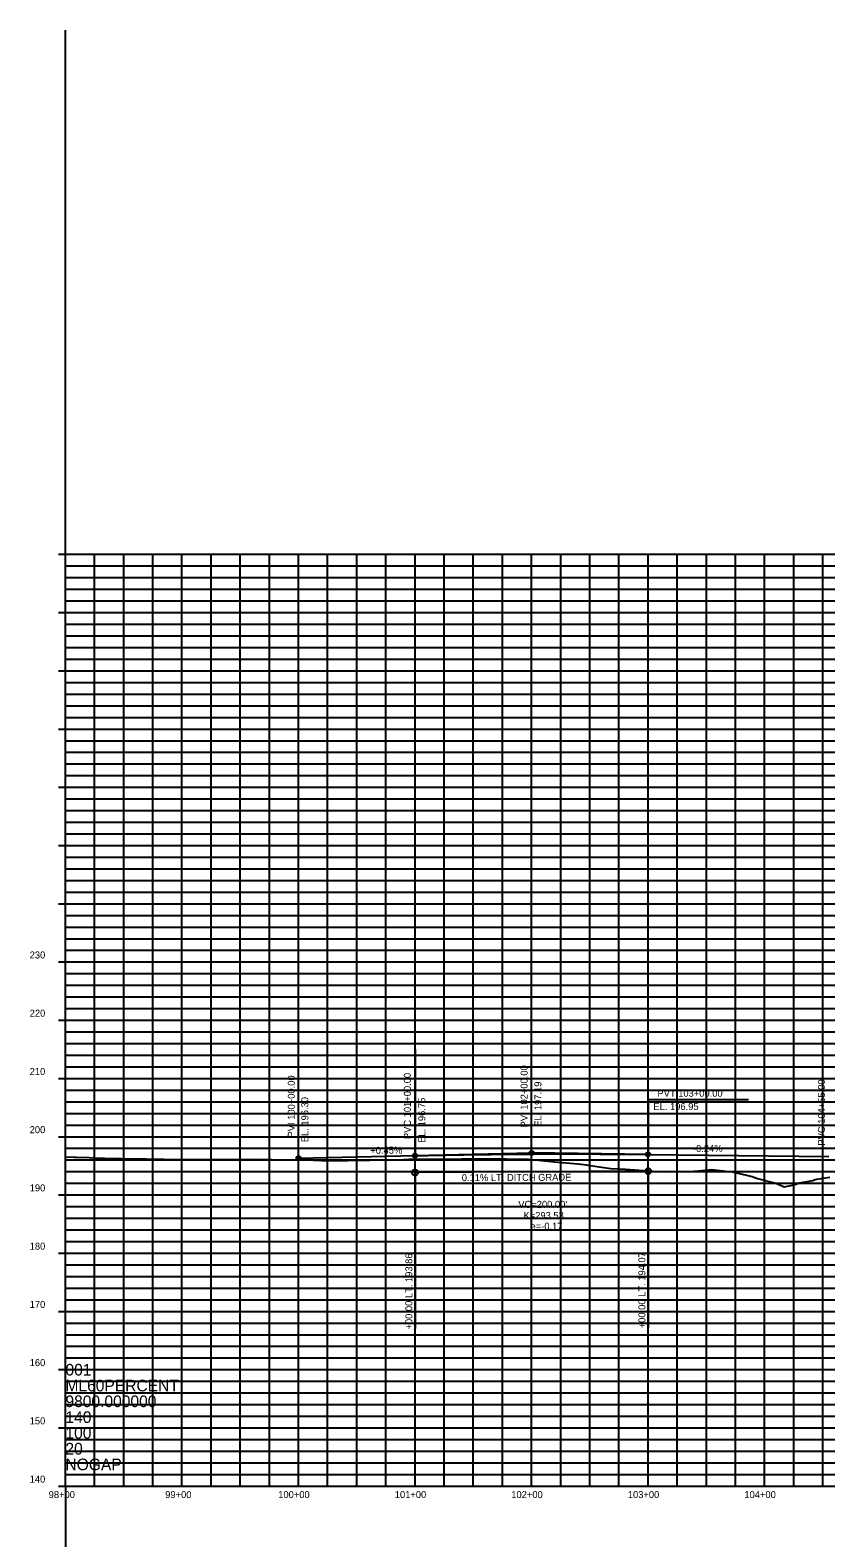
# Model space of a CAD drawing. Extents: x 1384498 to 1391279, y 1965973 to 1976560.
# Drawn here: x 1388219 to 1388901, y 1975265 to 1976560 of the extents above; entities that cross this region are included whole.
import ezdxf

# ---------------------------------------------------------------- set-up
doc = ezdxf.new("R2010")
doc.units = 0
for name, color, linetype in [('Default', 7, 'Continuous'), ('R_Axis_Annotation', 7, 'Continuous'), ('R_Exist Surface', 7, 'Continuous'), ('R_Grid', 7, 'Continuous'), ('R_Grid Annot', 7, 'Continuous'), ('R_Grid_Minor', 7, 'Continuous'), ('R_Vert Alg', 7, 'Continuous'), ('R_Vert Alg Annot', 7, 'Continuous')]:
    doc.layers.add(name, color=color, linetype=linetype)

msp = doc.modelspace()

# ---------------------------------------------------------------- linework, layer by layer
at = {"layer": 'Default'}
for q in [(1388248.8, 1976559.8), (1390648.8, 1975309.8), (1388248.8, 1974059.8)]:
    msp.add_line((1388248.8, 1975309.8), q, dxfattribs=at)
at = {"layer": 'R_Exist Surface'}
msp.add_lwpolyline([(1388248.8, 1975592.4), (1388256.2, 1975592.1), (1388258.4, 1975592.1), (1388269.2, 1975591.8), (1388273.4, 1975591.6), (1388282.2, 1975591.4), (1388288.4, 1975591.2), (1388296.8, 1975591), (1388303.4, 1975590.8), (1388313.1, 1975590.8), (1388318.4, 1975590.7), (1388328.7, 1975590.5), (1388333.4, 1975590.4), (1388337.8, 1975590.3), (1388348.4, 1975590.2), (1388352.2, 1975590.2), (1388363.4, 1975590.2), (1388366.2, 1975590.2), (1388378.4, 1975590.2), (1388384.7, 1975590.3), (1388393.4, 1975590.3), (1388406.3, 1975590.3), (1388408.4, 1975590.4), (1388410.8, 1975590.3), (1388423.4, 1975590.3), (1388426, 1975590.3), (1388438.4, 1975590), (1388439.1, 1975590), (1388442.9, 1975590), (1388451.8, 1975589.9), (1388453.4, 1975589.9), (1388461.8, 1975589.6), (1388468.4, 1975589.4), (1388476.7, 1975589.4), (1388483.4, 1975589.4), (1388490.7, 1975589.4), (1388498.4, 1975589.5), (1388500.4, 1975589.6), (1388503.8, 1975589.6), (1388509.9, 1975589.7), (1388513.5, 1975589.8), (1388518.3, 1975589.9), (1388523.5, 1975589.9), (1388526.1, 1975589.9), (1388528.5, 1975589.9), (1388533.7, 1975590), (1388539.1, 1975590.2), (1388541.4, 1975590.3), (1388543.6, 1975590.4), (1388548.3, 1975590.4), (1388552, 1975590.4), (1388558.7, 1975590.4), (1388561.5, 1975590.4), (1388563.6, 1975590.4), (1388573.8, 1975590.5), (1388574.1, 1975590.5), (1388588.8, 1975590.8), (1388596.3, 1975590.9), (1388598, 1975590.8), (1388604.1, 1975590.9), (1388613.2, 1975590.9), (1388618.8, 1975590.9), (1388627, 1975590.9), (1388640.4, 1975590.5), (1388641.3, 1975590.5), (1388643.2, 1975590.4), (1388646.3, 1975590.4), (1388666, 1975588.4), (1388668.6, 1975588.1), (1388688.6, 1975586.4), (1388693.6, 1975585.8), (1388708.7, 1975583.6), (1388716.7, 1975582.6), (1388729.5, 1975581.8), (1388740.8, 1975581.1), (1388757.5, 1975580), (1388764.5, 1975579.6), (1388775.8, 1975580.1), (1388780, 1975579.7), (1388791.8, 1975580.6), (1388803.6, 1975581.6), (1388805.6, 1975581.4), (1388805.8, 1975581.3), (1388818, 1975580), (1388819.9, 1975579.8), (1388838.2, 1975575.5), (1388842.7, 1975573.8), (1388858.4, 1975570), (1388865.5, 1975566.6), (1388874.1, 1975568.4), (1388878.7, 1975570.2), (1388890.2, 1975572.3), (1388892.3, 1975572.9), (1388893.7, 1975573.4), (1388904.8, 1975574.9)], dxfattribs=at)
at = {"layer": 'R_Grid'}
for p, q in [((1388248.8, 1975309.8), (1388248.8, 1976109.8)), ((1388248.8, 1976109.8), (1391048.8, 1976109.8)), ((1388248.8, 1976109.8), (1391048.8, 1976109.8)), ((1388248.8, 1975309.8), (1388248.8, 1976109.8)), ((1388348.8, 1975309.8), (1388348.8, 1976109.8)), ((1388448.8, 1975309.8), (1388448.8, 1976109.8)), ((1388548.8, 1975309.8), (1388548.8, 1976109.8)), ((1388648.8, 1975309.8), (1388648.8, 1976109.8)), ((1388748.8, 1975309.8), (1388748.8, 1976109.8)), ((1388848.8, 1975309.8), (1388848.8, 1976109.8)), ((1388248.8, 1976059.8), (1391048.8, 1976059.8)), ((1388248.8, 1976009.8), (1391048.8, 1976009.8)), ((1388248.8, 1975959.8), (1391048.8, 1975959.8)), ((1388248.8, 1975909.8), (1391048.8, 1975909.8)), ((1388248.8, 1975859.8), (1391048.8, 1975859.8)), ((1388248.8, 1975809.8), (1391048.8, 1975809.8)), ((1388248.8, 1975759.8), (1391048.8, 1975759.8)), ((1388248.8, 1975709.8), (1391048.8, 1975709.8)), ((1388248.8, 1975659.8), (1391048.8, 1975659.8)), ((1388248.8, 1975609.8), (1391048.8, 1975609.8)), ((1388248.8, 1975559.8), (1391048.8, 1975559.8)), ((1388248.8, 1975509.8), (1391048.8, 1975509.8)), ((1388248.8, 1975459.8), (1391048.8, 1975459.8)), ((1388248.8, 1975409.8), (1391048.8, 1975409.8)), ((1388248.8, 1975359.8), (1391048.8, 1975359.8)), ((1388248.8, 1975309.8), (1391048.8, 1975309.8))]:
    msp.add_line(p, q, dxfattribs=at)
at = {"layer": 'R_Grid Annot'}
for p, q in [((1388242.8, 1976109.8), (1388248.8, 1976109.8)), ((1388242.8, 1976109.8), (1388248.8, 1976109.8)), ((1388242.8, 1976059.8), (1388248.8, 1976059.8)), ((1388242.8, 1976009.8), (1388248.8, 1976009.8)), ((1388242.8, 1975959.8), (1388248.8, 1975959.8)), ((1388242.8, 1975909.8), (1388248.8, 1975909.8)), ((1388242.8, 1975859.8), (1388248.8, 1975859.8)), ((1388242.8, 1975809.8), (1388248.8, 1975809.8)), ((1388242.8, 1975759.8), (1388248.8, 1975759.8)), ((1388242.8, 1975709.8), (1388248.8, 1975709.8)), ((1388242.8, 1975659.8), (1388248.8, 1975659.8)), ((1388242.8, 1975609.8), (1388248.8, 1975609.8)), ((1388242.8, 1975559.8), (1388248.8, 1975559.8)), ((1388242.8, 1975509.8), (1388248.8, 1975509.8)), ((1388242.8, 1975459.8), (1388248.8, 1975459.8)), ((1388242.8, 1975409.8), (1388248.8, 1975409.8)), ((1388242.8, 1975359.8), (1388248.8, 1975359.8)), ((1388242.8, 1975309.8), (1388248.8, 1975309.8))]:
    msp.add_line(p, q, dxfattribs=at)
at = {"layer": 'R_Grid_Minor'}
for p, q in [((1388248.8, 1976099.8), (1391048.8, 1976099.8)), ((1388273.8, 1975309.8), (1388273.8, 1976109.8)), ((1388298.8, 1975309.8), (1388298.8, 1976109.8)), ((1388323.8, 1975309.8), (1388323.8, 1976109.8)), ((1388373.8, 1975309.8), (1388373.8, 1976109.8)), ((1388398.8, 1975309.8), (1388398.8, 1976109.8)), ((1388423.8, 1975309.8), (1388423.8, 1976109.8)), ((1388473.8, 1975309.8), (1388473.8, 1976109.8)), ((1388498.8, 1975309.8), (1388498.8, 1976109.8)), ((1388523.8, 1975309.8), (1388523.8, 1976109.8)), ((1388573.8, 1975309.8), (1388573.8, 1976109.8)), ((1388598.8, 1975309.8), (1388598.8, 1976109.8)), ((1388623.8, 1975309.8), (1388623.8, 1976109.8)), ((1388673.8, 1975309.8), (1388673.8, 1976109.8)), ((1388698.8, 1975309.8), (1388698.8, 1976109.8)), ((1388723.8, 1975309.8), (1388723.8, 1976109.8)), ((1388773.8, 1975309.8), (1388773.8, 1976109.8)), ((1388798.8, 1975309.8), (1388798.8, 1976109.8)), ((1388823.8, 1975309.8), (1388823.8, 1976109.8)), ((1388873.8, 1975309.8), (1388873.8, 1976109.8)), ((1388898.8, 1975309.8), (1388898.8, 1976109.8)), ((1388248.8, 1976089.8), (1391048.8, 1976089.8)), ((1388248.8, 1976079.8), (1391048.8, 1976079.8)), ((1388248.8, 1976069.8), (1391048.8, 1976069.8)), ((1388248.8, 1976049.8), (1391048.8, 1976049.8)), ((1388248.8, 1976039.8), (1391048.8, 1976039.8)), ((1388248.8, 1976029.8), (1391048.8, 1976029.8)), ((1388248.8, 1976019.8), (1391048.8, 1976019.8)), ((1388248.8, 1975999.8), (1391048.8, 1975999.8)), ((1388248.8, 1975989.8), (1391048.8, 1975989.8)), ((1388248.8, 1975979.8), (1391048.8, 1975979.8)), ((1388248.8, 1975969.8), (1391048.8, 1975969.8)), ((1388248.8, 1975949.8), (1391048.8, 1975949.8)), ((1388248.8, 1975939.8), (1391048.8, 1975939.8)), ((1388248.8, 1975929.8), (1391048.8, 1975929.8)), ((1388248.8, 1975919.8), (1391048.8, 1975919.8)), ((1388248.8, 1975899.8), (1391048.8, 1975899.8)), ((1388248.8, 1975889.8), (1391048.8, 1975889.8)), ((1388248.8, 1975879.8), (1391048.8, 1975879.8)), ((1388248.8, 1975869.8), (1391048.8, 1975869.8)), ((1388248.8, 1975849.8), (1391048.8, 1975849.8)), ((1388248.8, 1975839.8), (1391048.8, 1975839.8)), ((1388248.8, 1975829.8), (1391048.8, 1975829.8)), ((1388248.8, 1975819.8), (1391048.8, 1975819.8)), ((1388248.8, 1975799.8), (1391048.8, 1975799.8)), ((1388248.8, 1975789.8), (1391048.8, 1975789.8)), ((1388248.8, 1975779.8), (1391048.8, 1975779.8)), ((1388248.8, 1975769.8), (1391048.8, 1975769.8)), ((1388248.8, 1975749.8), (1391048.8, 1975749.8)), ((1388248.8, 1975739.8), (1391048.8, 1975739.8)), ((1388248.8, 1975729.8), (1391048.8, 1975729.8)), ((1388248.8, 1975719.8), (1391048.8, 1975719.8)), ((1388248.8, 1975699.8), (1391048.8, 1975699.8)), ((1388248.8, 1975689.8), (1391048.8, 1975689.8)), ((1388248.8, 1975679.8), (1391048.8, 1975679.8)), ((1388248.8, 1975669.8), (1391048.8, 1975669.8)), ((1388248.8, 1975649.8), (1391048.8, 1975649.8)), ((1388248.8, 1975639.8), (1391048.8, 1975639.8)), ((1388248.8, 1975629.8), (1391048.8, 1975629.8)), ((1388248.8, 1975619.8), (1391048.8, 1975619.8)), ((1388248.8, 1975599.8), (1391048.8, 1975599.8)), ((1388248.8, 1975589.8), (1391048.8, 1975589.8)), ((1388248.8, 1975579.8), (1391048.8, 1975579.8)), ((1388248.8, 1975569.8), (1391048.8, 1975569.8)), ((1388248.8, 1975549.8), (1391048.8, 1975549.8)), ((1388248.8, 1975539.8), (1391048.8, 1975539.8)), ((1388248.8, 1975529.8), (1391048.8, 1975529.8)), ((1388248.8, 1975519.8), (1391048.8, 1975519.8)), ((1388248.8, 1975499.8), (1391048.8, 1975499.8)), ((1388248.8, 1975489.8), (1391048.8, 1975489.8)), ((1388248.8, 1975479.8), (1391048.8, 1975479.8)), ((1388248.8, 1975469.8), (1391048.8, 1975469.8)), ((1388248.8, 1975449.8), (1391048.8, 1975449.8)), ((1388248.8, 1975439.8), (1391048.8, 1975439.8)), ((1388248.8, 1975429.8), (1391048.8, 1975429.8)), ((1388248.8, 1975419.8), (1391048.8, 1975419.8)), ((1388248.8, 1975399.8), (1391048.8, 1975399.8)), ((1388248.8, 1975389.8), (1391048.8, 1975389.8)), ((1388248.8, 1975379.8), (1391048.8, 1975379.8)), ((1388248.8, 1975369.8), (1391048.8, 1975369.8)), ((1388248.8, 1975349.8), (1391048.8, 1975349.8)), ((1388248.8, 1975339.8), (1391048.8, 1975339.8)), ((1388248.8, 1975329.8), (1391048.8, 1975329.8)), ((1388248.8, 1975319.8), (1391048.8, 1975319.8))]:
    msp.add_line(p, q, dxfattribs=at)
at = {"layer": 'R_Vert Alg'}
for p, q in [((1388748.8, 1975594.6), (1388903.8, 1975592.8)), ((1388448.8, 1975591.3), (1388548.8, 1975593.6)), ((1388748.8, 1975580.2), (1388548.8, 1975579.1))]:
    msp.add_line(p, q, dxfattribs=at)
msp.add_spline([(1388548.8, 1975593.6), (1388552.8, 1975593.7), (1388556.8, 1975593.7), (1388560.8, 1975593.8), (1388564.8, 1975593.9), (1388568.8, 1975594), (1388572.8, 1975594), (1388576.8, 1975594.1), (1388580.8, 1975594.2), (1388584.8, 1975594.3), (1388588.8, 1975594.3), (1388592.8, 1975594.4), (1388596.8, 1975594.4), (1388600.8, 1975594.5), (1388604.8, 1975594.5), (1388608.8, 1975594.6), (1388612.8, 1975594.6), (1388616.8, 1975594.7), (1388620.8, 1975594.7), (1388624.8, 1975594.8), (1388628.8, 1975594.8), (1388632.8, 1975594.8), (1388636.8, 1975594.9), (1388640.8, 1975594.9), (1388644.8, 1975594.9), (1388648.8, 1975594.9), (1388652.8, 1975595), (1388656.8, 1975595), (1388660.8, 1975595), (1388664.8, 1975595), (1388668.8, 1975595), (1388672.8, 1975595), (1388676.8, 1975595), (1388680.8, 1975595), (1388684.8, 1975595), (1388688.8, 1975595), (1388692.8, 1975595), (1388696.8, 1975595), (1388700.8, 1975595), (1388704.8, 1975595), (1388708.8, 1975594.9), (1388712.8, 1975594.9), (1388716.8, 1975594.9), (1388720.8, 1975594.9), (1388724.8, 1975594.8), (1388728.8, 1975594.8), (1388732.8, 1975594.8), (1388736.8, 1975594.7), (1388740.8, 1975594.7), (1388744.8, 1975594.7), (1388748.8, 1975594.6)], degree=3, dxfattribs=at)
at = {"layer": 'R_Vert Alg Annot'}
for p, q in [((1388448.8, 1975601.3), (1388448.8, 1975685.3)), ((1388548.8, 1975684.9), (1388548.8, 1975669.9)), ((1388648.8, 1975605.8), (1388648.8, 1975696.6)), ((1388548.8, 1975669.9), (1388548.8, 1975593.6)), ((1388835.1, 1975641.3), (1388748.8, 1975641.3)), ((1388748.8, 1975641.3), (1388748.8, 1975594.6)), ((1388448.8, 1975591.3), (1388448.8, 1975601.3)), ((1388548.8, 1975593.6), (1388648.8, 1975595.8)), ((1388648.8, 1975595.8), (1388648.8, 1975605.8)), ((1388748.8, 1975594.6), (1388648.8, 1975595.8)), ((1388548.8, 1975579.1), (1388548.8, 1975552.6)), ((1388748.8, 1975580.2), (1388748.8, 1975553.6)), ((1388548.8, 1975552.6), (1388548.8, 1975445)), ((1388748.8, 1975553.6), (1388748.8, 1975446))]:
    msp.add_line(p, q, dxfattribs=at)
for centre, radius in [((1388548.8, 1975593.6), 1.85), ((1388648.8, 1975595.8), 1.85), ((1388748.8, 1975594.6), 1.85), ((1388448.8, 1975591.3), 1.85), ((1388548.8, 1975579.1), 2.5), ((1388748.8, 1975580.2), 2.5)]:
    msp.add_circle(centre, radius, dxfattribs=at)

# ---------------------------------------------------------------- texts
at = {"layer": 'Default'}
for s, p in [('001', (1388248.8, 1975404.7)), ('ML60PERCENT', (1388248.8, 1975391.1)), ('9800.000000', (1388248.8, 1975377.6)), ('140', (1388248.8, 1975364)), ('100', (1388248.8, 1975350.5)), ('20', (1388248.8, 1975336.9)), ('NOGAP', (1388248.8, 1975323.4))]:
    msp.add_text(s, height=10, dxfattribs=at).set_placement(p)
at = {"layer": 'R_Axis_Annotation'}
for s, p in [('230', (1388218.1, 1975762.8)), ('220', (1388218.1, 1975712.8)), ('210', (1388218.1, 1975662.8)), ('200', (1388218.1, 1975612.8)), ('190', (1388218.1, 1975562.8)), ('180', (1388218.1, 1975512.8)), ('170', (1388218.1, 1975462.8)), ('160', (1388218.1, 1975412.8)), ('150', (1388218.1, 1975362.8)), ('140', (1388218.1, 1975312.8)), ('98+00', (1388234.4, 1975299.5)), ('99+00', (1388334.4, 1975299.5)), ('100+00', (1388431.4, 1975299.5)), ('101+00', (1388531.4, 1975299.5)), ('102+00', (1388631.4, 1975299.5)), ('103+00', (1388731.4, 1975299.5)), ('104+00', (1388831.4, 1975299.5))]:
    msp.add_text(s, height=6, dxfattribs=at).set_placement(p)
at = {"layer": 'R_Vert Alg Annot'}
for s, rotation, p in [('PVI 100+00.00', 90, (1388445.6, 1975609.1)), ('PVC 101+00.00', 90, (1388545.2, 1975607.7)), ('PVI 102+00.00', 90, (1388645.4, 1975617.8)), ('EL. 197.19', 90, (1388657.3, 1975618.3)), ('PVC 104+55.00', 90, (1388900.6, 1975602.1)), (' EL. 196.30', 90, (1388457.2, 1975602.8)), (' EL. 196.75', 90, (1388557.6, 1975602.2)), ('+0.45%', 0.4235, (1388510.4, 1975595)), ('-0.24%', 0.4235, (1388787.3, 1975596.6)), ('0.11% LT. DITCH GRADE', 0.222, (1388588.9, 1975571.6)), ('+00.00 LT. 193.86', 90, (1388546.5, 1975444.2)), ('+00.00 LT. 194.07', 90, (1388746.5, 1975445.3))]:
    msp.add_text(s, height=6, rotation=rotation, dxfattribs=at).set_placement(p)
for s, p in [('PVT 103+00.00', (1388756.8, 1975644.1)), (' EL. 196.95', (1388751.1, 1975632.7)), ("VC=200.00'", (1388637.4, 1975548.7)), ('K=293.53', (1388641.9, 1975539.2)), ('e=-0.17', (1388647.9, 1975529.9))]:
    msp.add_text(s, height=6, dxfattribs=at).set_placement(p)

doc.saveas('drawing.dxf')
